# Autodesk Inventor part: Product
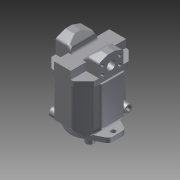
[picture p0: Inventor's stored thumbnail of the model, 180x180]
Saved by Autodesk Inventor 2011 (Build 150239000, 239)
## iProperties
Created: 2012-02
Part Number: Product
Document SubType Name: Modeling
Designer: khramov
Density: 1 g/cm^3
Стандарт преобразования: STEP AP203
Имя файла: VPPM-073.stp
Препроцессор: Mechanical Desktop 2011
Постпроцессор: Build: 239, Release: 2011 RTM - Date: Wed 02/17/2010
Отправленные единицы: миллиметр
Неопределенность: 1.0000000000000002e-06
Author: khramov
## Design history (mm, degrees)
feature "БазТело1"
sketch "Эскиз1"
  geometry: L1 (106.5, -30)-(33.983, -66.859) reference; L2 (106.5, 30)-(106.5, -30) reference; L3 (33.983, 66.859)-(106.5, 30) reference; L4 (-106.5, 30)-(-33.983, 66.859) reference; L5 (-106.5, -30)-(-106.5, 30) reference; L6 (-33.983, -66.859)-(-106.5, -30) reference; A1 r 75 centre (0, 0) between (33.983, 66.859) and (-33.983, 66.859) reference; A2 r 75 centre (0, 0) between (-33.983, -66.859) and (33.983, -66.859) reference
extrude "Выдавливание1" join sketch "Эскиз1" distance "d0" = 3.5; taper "d1" = 0 deg
sketch "Эскиз2"
  geometry: C1 r 62.5 at (0, 0); A1 r 75 centre (0, 0) between (33.983, 66.859) and (-33.983, 66.859) reference
  constraints: 1 centre point, 1 coincident
  dimensions: "d2" = 125 diameter of C1
extrude "Выдавливание2" join sketch "Эскиз2" distance "d3" = 9; taper "d4" = 0 deg
sketch "Эскиз3"
  geometry: C1 r 62.5 at (0, 0) reference; C2 r 16 at (0, 0)
  constraints: 1 centre point, 1 coincident
  dimensions: "d5" = 32 diameter of C2
extrude "Выдавливание3" join sketch "Эскиз3" distance "d6" = 51; taper "d7" = 0 deg
sketch "Эскиз4"
  geometry: L1 (106.5, 30)-(106.5, -30) reference; L2 (-106.5, -30)-(-106.5, 30) reference; L3 (106.5, 0)-(-106.5, 0); C1 r 62.5 at (0, 0) reference; C2 r 9 at (90, 0); C3 r 9 at (-90, 0)
  constraints: 2 centre point, 2 end point, 2 midpoint, 2 point on line
  dimensions: "d8" = 18 diameter of C2; "d9" = 18 diameter of C3; "d10" = 180 distance of C3.centre C2.centre; "d11" = 90 distance of C1.centre C2.centre
extrude "Выдавливание4" cut sketch "Эскиз4" stored distance "d12" = 51; taper "d13" = 0 deg
sketch "Эскиз5"
  geometry: L1 (141.5, -30)-(141.5, 10); L2 (141.5, 10)-(99.624, -30); L3 (51, -108.5)-(19, -108.5) reference; L4 (35, -108.5)-(35, 251.9); L5 (141.5, -30)-(99.624, -30); L6 (99.624, -30)-(123.5, -30) reference; L7 (-71.5, -30)-(-71.5, 10); L8 (-71.5, 10)-(-29.624, -30); L9 (-71.5, -30)-(-29.624, -30); 1 further point
  constraints: 14 end point, 3 symmetric about line, 1 collinear, 1 midpoint, 1 perpendicular
  dimensions: "d14" = 40 distance of L1.start L1.end
extrude "Выдавливание5" cut sketch "Эскиз5" distance "d15" = 300; taper "d16" = 0 deg
sketch "Эскиз6"
  geometry: L1 (-255.5, 31.366)-(-255.5, 63.366) reference; L2 (-255.5, 47.366)-(210.069, 47.366); L3 (-195.5, 77.366)-(-195.5, 17.366) reference; C1 r 25.4 at (39.5, 47.366); 1 further point
  constraints: 2 end point, 1 centre point, 1 midpoint, 1 perpendicular, 1 point on line
  dimensions: "d17" = 50.8 diameter of C1; "d18" = 235 distance from line of C1.centre L3
extrude "Выдавливание6" cut sketch "Эскиз6" distance "d19" = 50; taper "d20" = 0 deg
sketch "Эскиз7"
  geometry: L1 (18, 86.266)-(61, 86.266); L2 (61, 86.266)-(61, 8.466); L3 (61, 8.466)-(18, 8.466); L4 (18, 8.466)-(18, 86.266); L5 (39.5, 47.366)-(18, 47.366); L6 (39.5, 47.366)-(39.5, 86.266); C1 r 25.4 at (39.5, 47.366) reference; 5 further points
  constraints: 12 end point, 4 coincident, 2 horizontal, 2 midpoint, 2 parallel, 1 perpendicular, 1 vertical
  dimensions: "d21" = 43 distance of L1.start L1.end; "d22" = 77.8 distance of L3.end L1.start
hole "Отверстие1" sketch "Эскиз7" at (18, 86.266), (61, 86.266), (61, 8.466), (18, 8.466) diameter "d23" = 10.106; stored, may be unused: countersink angle "d27" = 90 deg, drill point angle "d29" = 118 deg; dims "d24" = 23, "d25" = 13, "d26" = 2, "d28" = 25
sketch "Эскиз8"
  geometry: L1 (252.207, 47.366)-(-186.773, 47.366); L2 (255.5, 63.366)-(255.5, 31.366) reference; L3 (195.5, 17.366)-(195.5, 77.366) reference; C1 r 16 at (-39.5, 47.366); 1 further point
  constraints: 2 end point, 1 centre point, 1 perpendicular, 1 point on line
  dimensions: "d30" = 32 diameter of C1; "d31" = 235 distance from line of L3 C1.centre
extrude "Выдавливание7" cut sketch "Эскиз8" distance "d32" = 50; taper "d33" = 0 deg
sketch "Эскиз9"
  geometry: L1 (-55.35, 80.716)-(-23.65, 80.716); L2 (-23.65, 80.716)-(-23.65, 14.016); L3 (-23.65, 14.016)-(-55.35, 14.016); L4 (-55.35, 14.016)-(-55.35, 80.716); L5 (-39.5, 47.366)-(-55.35, 47.366); L6 (-39.5, 80.716)-(-39.5, 47.366); C1 r 16 at (-39.5, 47.366) reference; 5 further points
  constraints: 12 end point, 4 coincident, 3 parallel, 2 horizontal, 2 midpoint, 1 perpendicular
  dimensions: "d34" = 31.7 distance of L1.start L1.end; "d35" = 66.7 distance of L3.end L1.start
hole "Отверстие2" sketch "Эскиз9" at (-55.35, 80.716), (-23.65, 80.716), (-23.65, 14.016), (-55.35, 14.016) diameter "d36" = 11.835; stored, may be unused: countersink angle "d40" = 90 deg, drill point angle "d42" = 118 deg; dims "d37" = 23, "d38" = 15, "d39" = 2, "d41" = 25
sketch "Эскиз10"
  geometry: L1 (6.275, 111.808)-(15.085, 111.808); L2 (15.085, 111.808)-(15.085, 105.88); L3 (15.085, 105.88)-(6.275, 105.88); L4 (6.275, 105.88)-(6.275, 111.808); 1 further point
  constraints: 2 other
extrude "Выдавливание8" cut sketch "Эскиз10" distance "d43" = 0.5; taper "d44" = 0 deg
sketch "Эскиз11"
  geometry: L1 (-16.401, 110.753)-(-4.511, 110.753); L2 (-4.511, 110.753)-(-4.511, 102.881); L3 (-4.511, 102.881)-(-16.401, 102.881); L4 (-16.401, 102.881)-(-16.401, 110.753); 1 further point
  constraints: 2 other
extrude "Выдавливание9" cut sketch "Эскиз11" distance "d45" = 0.5; taper "d46" = 0 deg
sketch "Эскиз12"
  geometry: L1 (-195.5, 75)-(-195.5, 15) reference; C1 r 15 at (-151.5, -30.563); 1 further point
  constraints: 1 centre point
  dimensions: "d47" = 44 distance from line of C1.centre L1; "d48" = 30 diameter of C1
extrude "Выдавливание10" join sketch "Эскиз12" distance "d49" = 50; taper "d50" = 0 deg
sketch "Эскиз13"
  geometry: C1 r 15 at (0, 0) reference; C2 r 17.615 at (0, 0); 1 further point
  constraints: 1 centre point, 1 coincident
extrude "Выдавливание11" cut sketch "Эскиз13" distance "d51" = 20; taper "d52" = 0 deg
sketch "Эскиз14"
  geometry: C1 r 15 at (0, 0) reference; 2 further points
  constraints: 1 coincident
hole "Отверстие3" sketch "Эскиз14" at (0, 0) diameter "d53" = 18.631; stored, may be unused: countersink angle "d57" = 90 deg, drill point angle "d59" = 118 deg; dims "d54" = 23, "d55" = 20, "d56" = 2, "d58" = 25
fillet "Сопряжение1" dims "d60" = 20
fillet "Сопряжение2" dims "d61" = 10
fillet "Сопряжение3" dims "d62" = 10
fillet "Сопряжение4" dims "d63" = 10
sketch "Эскиз15"
  geometry: C1 r 15 at (148, 113.339); 2 further points; 1 other entity
  constraints: 1 centre point, 1 coincident, 1 other
  dimensions: "d64" = 30 diameter of C1
extrude "Выдавливание12" join sketch "Эскиз15" distance "d65" = 50; taper "d66" = 0 deg
sketch "Эскиз16"
  geometry: C1 r 15 at (0, 0) reference; 1 further point
extrude "Выдавливание13" cut sketch "Эскиз16" distance "d67" = 15; taper "d68" = 0 deg
sketch "Эскиз17"
  geometry: C1 r 15 at (0, 0) reference; 2 further points
  constraints: 1 coincident
hole "Отверстие4" sketch "Эскиз17" at (0, 0) diameter "d69" = 18.631; stored, may be unused: countersink angle "d73" = 90 deg, drill point angle "d75" = 118 deg; dims "d70" = 23, "d71" = 20, "d72" = 2, "d74" = 25
chamfer "Фаска1" distance "d76" = 1; stored, may be unused: second distance "d77" = 2, angle "d78" = 45 deg
fillet "Сопряжение5" dims "d79" = 15
node "A9C7"
